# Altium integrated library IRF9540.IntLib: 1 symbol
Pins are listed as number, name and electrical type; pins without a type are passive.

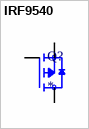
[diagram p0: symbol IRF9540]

## IRF9540
designator Q?
P-Channel 100 V 19A (Tc) 3.7W (Ta), 150W (Tc) Surface Mount DÂ²PAK (TO-263); MF: Vishay; MP: IRF9540
footprint TO254P1052X465X1989-3
pins: 1 G, 2 D, 3 S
